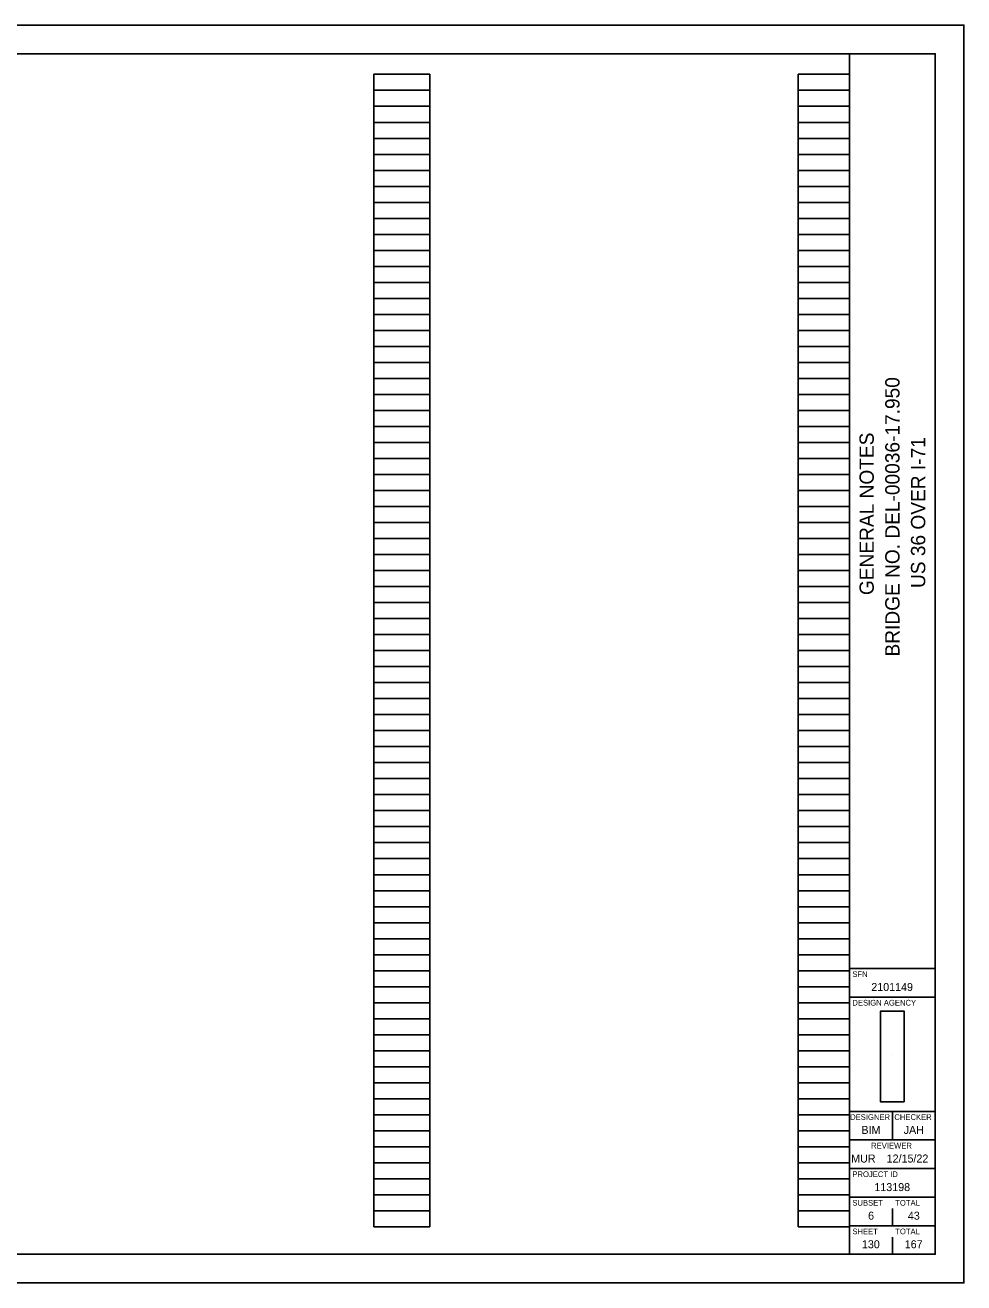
# Model space of a CAD drawing. Extents: x 0 to 90.2, y -3.7 to 22.
# Drawn here: x 17.58 to 34, y 0 to 22 of the extents above; entities that cross this region are included whole.
import ezdxf

# ---------------------------------------------------------------- set-up
doc = ezdxf.new("R2010")
doc.units = 0
for name, color, linetype in [('SH_Border', 7, 'Continuous'), ('SH_Cut_Line', 7, 'Continuous'), ('SH_Data', 7, 'Continuous'), ('SH_Text', 7, 'Continuous')]:
    doc.layers.add(name, color=color, linetype=linetype)

msp = doc.modelspace()

# ---------------------------------------------------------------- linework, layer by layer
at = {"layer": 'SH_Border'}
for p, q in [((32, 0.5), (32, 21.5)), ((32, 5.5), (33.5, 5.5)), ((32, 5), (33.5, 5)), ((32, 3), (33.5, 3)), ((32.75, 3), (32.75, 2.5)), ((32, 2.5), (33.5, 2.5)), ((32, 2), (33.5, 2)), ((32, 1.5), (33.5, 1.5)), ((32, 1), (33.5, 1))]:
    msp.add_line(p, q, dxfattribs=at)
msp.add_lwpolyline([(1.5, 21.5), (33.5, 21.5), (33.5, 0.5), (1.5, 0.5)], close=True, dxfattribs=at)
at = {"layer": 'SH_Cut_Line'}
msp.add_lwpolyline([(0, 0), (34, 0), (34, 22), (0, 22)], close=True, dxfattribs=at)
at = {"layer": 'SH_Data'}
for p, q in [((23.68, 0.98), (23.68, 21.14)), ((23.68, 21.14), (24.66, 21.14)), ((24.66, 0.98), (24.66, 21.14)), ((31.1, 0.98), (31.1, 21.14)), ((31.1, 21.14), (32, 21.14)), ((32, 0.98), (32, 21.14)), ((23.68, 20.86), (24.66, 20.86)), ((31.1, 20.86), (32, 20.86)), ((23.68, 20.58), (24.66, 20.58)), ((31.1, 20.58), (32, 20.58)), ((23.68, 20.3), (24.66, 20.3)), ((31.1, 20.3), (32, 20.3)), ((23.68, 20.02), (24.66, 20.02)), ((31.1, 20.02), (32, 20.02)), ((23.68, 19.74), (24.66, 19.74)), ((31.1, 19.74), (32, 19.74)), ((23.68, 19.46), (24.66, 19.46)), ((31.1, 19.46), (32, 19.46)), ((23.68, 19.18), (24.66, 19.18)), ((31.1, 19.18), (32, 19.18)), ((23.68, 18.9), (24.66, 18.9)), ((31.1, 18.9), (32, 18.9)), ((23.68, 18.62), (24.66, 18.62)), ((31.1, 18.62), (32, 18.62)), ((23.68, 18.34), (24.66, 18.34)), ((31.1, 18.34), (32, 18.34)), ((23.68, 18.06), (24.66, 18.06)), ((31.1, 18.06), (32, 18.06)), ((23.68, 17.78), (24.66, 17.78)), ((31.1, 17.78), (32, 17.78)), ((23.68, 17.5), (24.66, 17.5)), ((31.1, 17.5), (32, 17.5)), ((23.68, 17.22), (24.66, 17.22)), ((31.1, 17.22), (32, 17.22)), ((23.68, 16.94), (24.66, 16.94)), ((31.1, 16.94), (32, 16.94)), ((23.68, 16.66), (24.66, 16.66)), ((31.1, 16.66), (32, 16.66)), ((23.68, 16.38), (24.66, 16.38)), ((31.1, 16.38), (32, 16.38)), ((23.68, 16.1), (24.66, 16.1)), ((31.1, 16.1), (32, 16.1)), ((23.68, 15.82), (24.66, 15.82)), ((31.1, 15.82), (32, 15.82)), ((23.68, 15.54), (24.66, 15.54)), ((31.1, 15.54), (32, 15.54)), ((23.68, 15.26), (24.66, 15.26)), ((31.1, 15.26), (32, 15.26)), ((23.68, 14.98), (24.66, 14.98)), ((31.1, 14.98), (32, 14.98)), ((23.68, 14.7), (24.66, 14.7)), ((31.1, 14.7), (32, 14.7)), ((23.68, 14.42), (24.66, 14.42)), ((31.1, 14.42), (32, 14.42)), ((23.68, 14.14), (24.66, 14.14)), ((31.1, 14.14), (32, 14.14)), ((23.68, 13.86), (24.66, 13.86)), ((31.1, 13.86), (32, 13.86)), ((23.68, 13.58), (24.66, 13.58)), ((31.1, 13.58), (32, 13.58)), ((23.68, 13.3), (24.66, 13.3)), ((31.1, 13.3), (32, 13.3)), ((23.68, 13.02), (24.66, 13.02)), ((31.1, 13.02), (32, 13.02)), ((23.68, 12.74), (24.66, 12.74)), ((31.1, 12.74), (32, 12.74)), ((23.68, 12.46), (24.66, 12.46)), ((31.1, 12.46), (32, 12.46)), ((23.68, 12.18), (24.66, 12.18)), ((31.1, 12.18), (32, 12.18)), ((23.68, 11.9), (24.66, 11.9)), ((31.1, 11.9), (32, 11.9)), ((23.68, 11.62), (24.66, 11.62)), ((31.1, 11.62), (32, 11.62)), ((23.68, 11.34), (24.66, 11.34)), ((31.1, 11.34), (32, 11.34)), ((23.68, 11.06), (24.66, 11.06)), ((31.1, 11.06), (32, 11.06)), ((23.68, 10.78), (24.66, 10.78)), ((31.1, 10.78), (32, 10.78)), ((23.68, 10.5), (24.66, 10.5)), ((31.1, 10.5), (32, 10.5)), ((23.68, 10.22), (24.66, 10.22)), ((31.1, 10.22), (32, 10.22)), ((23.68, 9.94), (24.66, 9.94)), ((31.1, 9.94), (32, 9.94)), ((23.68, 9.66), (24.66, 9.66)), ((31.1, 9.66), (32, 9.66)), ((23.68, 9.38), (24.66, 9.38)), ((31.1, 9.38), (32, 9.38)), ((23.68, 9.1), (24.66, 9.1)), ((31.1, 9.1), (32, 9.1)), ((23.68, 8.82), (24.66, 8.82)), ((31.1, 8.82), (32, 8.82)), ((23.68, 8.54), (24.66, 8.54)), ((31.1, 8.54), (32, 8.54)), ((23.68, 8.26), (24.66, 8.26)), ((31.1, 8.26), (32, 8.26)), ((23.68, 7.98), (24.66, 7.98)), ((31.1, 7.98), (32, 7.98)), ((23.68, 7.7), (24.66, 7.7)), ((31.1, 7.7), (32, 7.7)), ((23.68, 7.42), (24.66, 7.42)), ((31.1, 7.42), (32, 7.42)), ((23.68, 7.14), (24.66, 7.14)), ((31.1, 7.14), (32, 7.14)), ((23.68, 6.86), (24.66, 6.86)), ((31.1, 6.86), (32, 6.86)), ((23.68, 6.58), (24.66, 6.58)), ((31.1, 6.58), (32, 6.58)), ((23.68, 6.3), (24.66, 6.3)), ((31.1, 6.3), (32, 6.3)), ((23.68, 6.02), (24.66, 6.02)), ((31.1, 6.02), (32, 6.02)), ((23.68, 5.74), (24.66, 5.74)), ((31.1, 5.74), (32, 5.74)), ((23.68, 5.46), (24.66, 5.46)), ((31.1, 5.46), (32, 5.46)), ((23.68, 5.18), (24.66, 5.18)), ((31.1, 5.18), (32, 5.18)), ((23.68, 4.9), (24.66, 4.9)), ((31.1, 4.9), (32, 4.9)), ((23.68, 4.62), (24.66, 4.62)), ((31.1, 4.62), (32, 4.62)), ((23.68, 4.34), (24.66, 4.34)), ((31.1, 4.34), (32, 4.34)), ((23.68, 4.06), (24.66, 4.06)), ((31.1, 4.06), (32, 4.06)), ((32.75, 4), (32.75, 4)), ((23.68, 3.78), (24.66, 3.78)), ((31.1, 3.78), (32, 3.78)), ((23.68, 3.5), (24.66, 3.5)), ((31.1, 3.5), (32, 3.5)), ((23.68, 3.22), (24.66, 3.22)), ((31.1, 3.22), (32, 3.22)), ((23.68, 2.94), (24.66, 2.94)), ((31.1, 2.94), (32, 2.94)), ((23.68, 2.66), (24.66, 2.66)), ((31.1, 2.66), (32, 2.66)), ((23.68, 2.38), (24.66, 2.38)), ((31.1, 2.38), (32, 2.38)), ((23.68, 2.1), (24.66, 2.1)), ((31.1, 2.1), (32, 2.1)), ((23.68, 1.82), (24.66, 1.82)), ((31.1, 1.82), (32, 1.82)), ((23.68, 1.54), (24.66, 1.54)), ((31.1, 1.54), (32, 1.54)), ((23.68, 1.26), (24.66, 1.26)), ((31.1, 1.26), (32, 1.26)), ((32.75, 1), (32.75, 1.3)), ((23.68, 0.98), (24.66, 0.98)), ((31.1, 0.98), (32, 0.98)), ((32.375, 0.675), (32.375, 0.675)), ((32.75, 0.5), (32.75, 0.8))]:
    msp.add_line(p, q, dxfattribs=at)
at = {"layer": 'SH_Text'}
msp.add_lwpolyline([(32.956, 3.164), (32.956, 4.754), (32.544, 4.754), (32.544, 3.164)], close=True, dxfattribs=at)

# ---------------------------------------------------------------- texts
at = {"layer": 'SH_Data'}
for s, p in [('BRIDGE NO. DEL-00036-17.950', (32.875, 10.956)), ('GENERAL NOTES', (32.425, 12.031)), ('US 36 OVER I-71', (33.325, 12.154))]:
    msp.add_text(s, height=0.25, rotation=90, dxfattribs=at).set_placement(p)
for s, height, p in [('SFN', 0.1, (32.05, 5.35)), ('2101149', 0.14, (32.381, 5.105)), ('DESIGN AGENCY', 0.1, (32.05, 4.85)), ('DESIGNER', 0.1, (32.011, 2.85)), ('CHECKER', 0.1, (32.784, 2.85)), ('BIM', 0.14, (32.208, 2.605)), ('JAH', 0.14, (32.948, 2.605)), ('REVIEWER', 0.1, (32.378, 2.35)), ('MUR', 0.14, (32.029, 2.105)), ('12/15/22', 0.14, (32.65, 2.105)), ('PROJECT ID', 0.1, (32.05, 1.85)), ('113198', 0.14, (32.435, 1.605)), ('SUBSET', 0.1, (32.05, 1.35)), ('TOTAL', 0.1, (32.8, 1.35)), ('6', 0.14, (32.325, 1.105)), ('43', 0.14, (33.021, 1.105)), ('SHEET', 0.1, (32.05, 0.85)), ('TOTAL', 0.1, (32.8, 0.85)), ('130', 0.14, (32.217, 0.605)), ('167', 0.14, (32.966, 0.605))]:
    msp.add_text(s, height=height, dxfattribs=at).set_placement(p)

doc.saveas('drawing.dxf')
